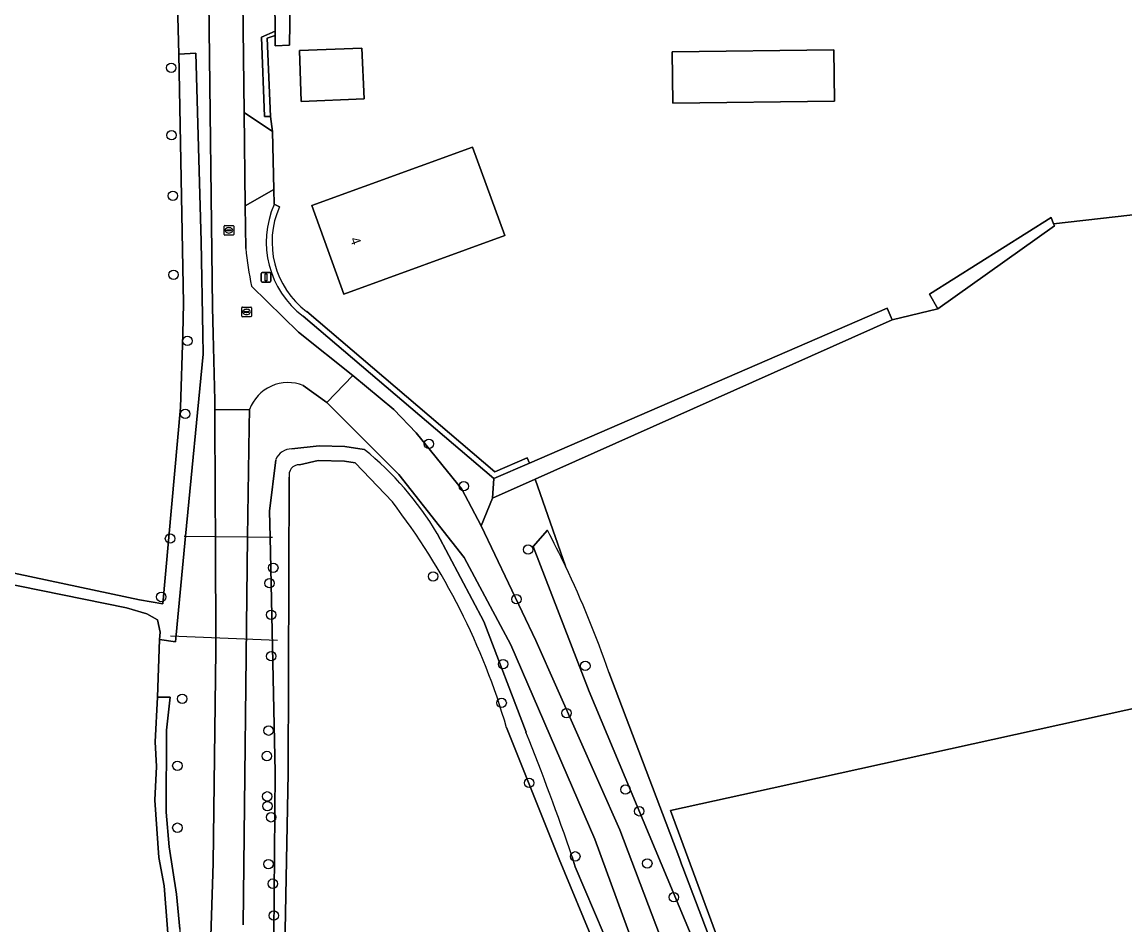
# Model space of a CAD drawing. Extents: x 163859 to 164644, y 379566 to 382155.
# Drawn here: x 164422.2 to 164536.6, y 381404.3 to 381497.9 of the extents above; entities that cross this region are included whole.
import ezdxf

# ---------------------------------------------------------------- set-up
doc = ezdxf.new("R2010")
doc.units = 0
for name, color, linetype in [('IMGEO_Boom', 7, 'Continuous'), ('IMGEO_Brandkraan', 7, 'Continuous'), ('IMGEO_Duiker', 7, 'Continuous'), ('IMGEO_Erf', 7, 'Continuous'), ('IMGEO_Grasland_agrarisch', 7, 'Continuous'), ('IMGEO_Grasland_overig', 7, 'Continuous'), ('IMGEO_Groenvoorziening', 7, 'Continuous'), ('IMGEO_Haag', 7, 'Continuous'), ('IMGEO_Lichtmast', 7, 'Continuous'), ('IMGEO_Loofbos', 7, 'Continuous'), ('IMGEO_Pand', 7, 'Continuous'), ('IMGEO_Pand_nummerreeks', 7, 'Continuous'), ('IMGEO_Rijbaan_lokaal_gesloten', 7, 'Continuous'), ('IMGEO_Rijbaan_lokaal_onverhard', 7, 'Continuous'), ('IMGEO_Rioolput', 7, 'Continuous'), ('IMGEO_Voetpad_open', 7, 'Continuous'), ('IMGEO_Waterloop', 7, 'Continuous')]:
    doc.layers.add(name, color=color, linetype=linetype)

msp = doc.modelspace()

# ---------------------------------------------------------------- linework, layer by layer
at = {"layer": 'IMGEO_Boom'}
for centre in [(164437.68, 381493.12), (164437.72, 381486.12), (164437.86, 381479.85), (164437.93, 381471.66), (164439.36, 381464.81), (164439.13, 381457.24), (164464.41, 381454.14), (164468.02, 381449.75), (164437.56, 381444.32), (164474.7, 381443.18), (164448.27, 381441.3), (164464.84, 381440.4), (164447.88, 381439.7), (164436.65, 381438.27), (164473.49, 381438.04), (164448.04, 381436.43), (164448.05, 381432.13), (164472.1, 381431.32), (164480.63, 381431.13), (164438.82, 381427.72), (164471.95, 381427.29), (164478.67, 381426.24), (164447.78, 381424.42), (164447.61, 381421.79), (164438.32, 381420.78), (164474.8, 381419.01), (164484.79, 381418.31), (164447.64, 381417.61), (164447.66, 381416.6), (164486.22, 381416.06), (164448.04, 381415.44), (164438.32, 381414.36), (164479.59, 381411.39), (164447.77, 381410.59), (164487.06, 381410.66), (164448.22, 381408.56), (164489.8, 381407.16), (164448.32, 381405.25)]:
    msp.add_circle(centre, 0.489, dxfattribs=at)
at = {"layer": 'IMGEO_Brandkraan'}
for p, q in [((164445, 381467.39), (164445, 381468.24)), ((164445.07, 381468.31), (164445.92, 381468.31)), ((164445.48, 381468.09), (164445.51, 381468.09)), ((164446, 381468.24), (164446, 381467.39)), ((164445.92, 381467.31), (164445.07, 381467.31)), ((164445.25, 381467.81), (164445.25, 381467.82)), ((164445.69, 381467.77), (164445.29, 381467.77)), ((164445.3, 381467.86), (164445.7, 381467.86)), ((164445.51, 381467.53), (164445.48, 381467.53)), ((164445.74, 381467.82), (164445.74, 381467.81))]:
    msp.add_line(p, q, dxfattribs=at)
for points in [[(164445, 381467.39), (164445, 381468.24)], [(164445.07, 381468.31), (164445.92, 381468.31)], [(164446, 381468.24), (164446, 381467.39)], [(164445.92, 381467.31), (164445.07, 381467.31)]]:
    msp.add_lwpolyline(points, dxfattribs=at)
for centre, radius, start, end in [((164445.07, 381468.24), 0.0765, 91.552, 178.448), ((164445.07, 381468.24), 0.0765, 91.552, 178.448), ((164445.92, 381468.24), 0.0765, 1.552, 88.448), ((164445.92, 381468.24), 0.0765, 1.552, 88.448), ((164445.07, 381467.39), 0.0765, 181.552, 268.448), ((164445.07, 381467.39), 0.0765, 181.552, 268.448), ((164445.3, 381467.82), 0.0403, 85.8775, 175.7526), ((164445.29, 381467.81), 0.0366, 178.938, 274.7102), ((164445.7, 381467.81), 0.043, 264.8664, 352.4533), ((164445.7, 381467.82), 0.0386, 1.7309, 96.639), ((164445.92, 381467.39), 0.0765, 271.552, 358.448), ((164445.92, 381467.39), 0.0765, 271.552, 358.448)]:
    msp.add_arc(centre, radius, start, end, dxfattribs=at)
for centre, major_axis, ratio, start_param, end_param in [((164445.48, 381467.81), (-0.387, 0.002), 0.722429, 4.712389, 7.853982), ((164445.51, 381467.81), (-0.39, 0.002), 0.717154, 1.570796, 4.712389)]:
    msp.add_ellipse(centre, major_axis=major_axis, ratio=ratio, start_param=start_param, end_param=end_param, dxfattribs=at)
at = {"layer": 'IMGEO_Duiker'}
for points in [[(164439.02, 381444.59), (164439.18, 381444.59), (164442.26, 381444.54), (164445.61, 381444.5), (164447.94, 381444.47), (164448.19, 381444.46)], [(164437.61, 381434.25), (164448.69, 381433.81)]]:
    msp.add_lwpolyline(points, dxfattribs=at)
at = {"layer": 'IMGEO_Erf'}
for points in [[(164450.01, 381500), (164449.96, 381495.46), (164448.45, 381495.4), (164448.45, 381496.45), (164447.62, 381496.18), (164447.99, 381488.08), (164448.2, 381486.51), (164448.33, 381480.51), (164448.37, 381478.97), (164448.92, 381478.72)], [(164451.73, 381467.85), (164471.25, 381451.25), (164474.6, 381452.7), (164474.84, 381452.15), (164511.94, 381468.21), (164512.46, 381467.01), (164517.19, 381468.15), (164516.33, 381469.65), (164528.93, 381477.6), (164529.2, 381476.95), (164546.85, 381478.96), (164550.19, 381479.28), (164572.08, 381481.36), (164589.1, 381482.68), (164601.73, 381483.93), (164603.35, 381484.14), (164603.26, 381486.4), (164606.33, 381486.63), (164606.55, 381484.56), (164606.85, 381484.6), (164606.85, 381484.81), (164606.82, 381486.07), (164607.05, 381486.1), (164606.79, 381500)]]:
    msp.add_lwpolyline(points, dxfattribs=at)
for points in [[(164457.68, 381489.91), (164451.15, 381489.61), (164450.97, 381494.89), (164457.45, 381495.15)], [(164506.46, 381489.64), (164489.69, 381489.43), (164489.62, 381494.77), (164506.39, 381494.98)], [(164472.27, 381475.73), (164455.6, 381469.67), (164452.28, 381478.83), (164468.94, 381484.89)], [(164565.06, 381406.39), (164564.53, 381407.1), (164559.87, 381421.34), (164557.52, 381431.13), (164500, 381418.46), (164489.46, 381416.14), (164495.45, 381399.95), (164500, 381401.35), (164503.1, 381402.3), (164503.54, 381401.07), (164504.8, 381397.62), (164505.66, 381395.29), (164507.47, 381390.32), (164518.04, 381364.93), (164522.77, 381352.02), (164528.1, 381339.46), (164564.56, 381341.91), (164578.44, 381343.7), (164575.05, 381361.38)]]:
    msp.add_lwpolyline(points, close=True, dxfattribs=at)
msp.add_arc((164457.2, 381475.06), 9.06, 156.1781, 232.8221, dxfattribs=at)
at = {"layer": 'IMGEO_Grasland_agrarisch'}
msp.add_lwpolyline([(164483.06, 381430.48), (164490.42, 381411.1), (164490.61, 381410.59), (164490.75, 381410.23), (164494.4, 381400.61), (164495.14, 381398.66), (164503.54, 381401.07), (164503.1, 381402.3), (164500, 381401.35), (164495.45, 381399.95), (164489.46, 381416.14), (164500, 381418.46), (164557.52, 381431.13), (164557.45, 381431.4), (164557.26, 381432.21), (164549, 381466.6), (164546.85, 381478.96), (164529.2, 381476.95), (164529.29, 381476.74), (164517.19, 381468.15), (164512.46, 381467.01), (164475.43, 381450.48), (164478.57, 381441.47)], dxfattribs=at)
msp.add_arc((164385.47, 381397.01), 103.17, 18.9285, 25.5241, dxfattribs=at)
at = {"layer": 'IMGEO_Grasland_overig'}
msp.add_lwpolyline([(164448.45, 381496.92), (164447.04, 381496.29), (164447.36, 381488.05), (164447.99, 381488.08), (164447.62, 381496.18), (164448.45, 381496.45)], close=True, dxfattribs=at)
at = {"layer": 'IMGEO_Groenvoorziening'}
for points in [[(164437.62, 381342.51), (164440.93, 381376.03), (164442.03, 381410.67), (164442.31, 381432.69), (164442.26, 381444.54), (164442.24, 381448.35), (164442.22, 381457.68), (164442.22, 381458.62), (164442.05, 381465.53), (164441.98, 381468.27), (164441.6, 381500), (164440.42, 381600.95)], [(164438.34, 381499.7), (164438.46, 381494.53), (164440.25, 381494.63), (164440.8, 381475.11), (164440.95, 381465.52), (164440.98, 381463.45), (164439.18, 381444.59), (164438.14, 381433.63), (164436.48, 381433.86), (164436.26, 381427.88), (164437.58, 381427.9), (164437.21, 381424.46), (164437.16, 381415.96), (164437.47, 381412.38), (164438.23, 381407.47), (164438.58, 381403.85), (164438.66, 381393.57), (164438.49, 381387.99), (164438.01, 381382.93), (164434.81, 381360.28), (164434.48, 381356.02), (164434.38, 381351.46), (164434.92, 381340.08), (164434.91, 381333.02)], [(164448.37, 381478.97), (164448.33, 381480.51), (164445.36, 381478.81), (164445.42, 381474.39)], [(164448.92, 381478.72), (164448.37, 381478.97)], [(164446.02, 381470.48), (164450.9, 381465.73), (164456.53, 381461.21), (164460.78, 381457.7), (164463.09, 381455.28), (164467.82, 381449.45), (164469.83, 381445.64), (164471, 381448.5), (164471.14, 381450.55), (164451.35, 381467.38)], [(164451.35, 381467.38), (164471.14, 381450.55), (164474.84, 381452.15), (164474.6, 381452.7), (164471.25, 381451.25), (164451.73, 381467.85)], [(164453.83, 381458.42), (164451.38, 381460.19)], [(164445.79, 381457.7), (164445.75, 381455.9), (164445.61, 381444.5), (164445.14, 381404.29)], [(164479.27, 381411.35), (164479.59, 381410.3), (164483.6, 381400.91), (164486.37, 381393.84), (164485.77, 381393.51), (164485.33, 381393.26), (164486.82, 381389.49), (164487.45, 381389.67), (164488.22, 381389.88), (164490.06, 381391.38), (164489.58, 381392.13), (164488.52, 381394.29), (164481.62, 381413.16), (164472.89, 381433.3), (164468.06, 381442.36), (164461.3, 381450.96), (164453.83, 381458.42)], [(164450.2, 381453.62), (164453.04, 381453.95), (164455.68, 381453.86), (164457.71, 381453.56)], [(164444.13, 381379.08), (164441.34, 381342.21), (164440.75, 381334.49), (164440.65, 381333.45), (164440.79, 381332.88), (164440.97, 381332.32), (164441.21, 381331.78), (164441.49, 381331.26), (164441.81, 381330.78), (164442.18, 381330.32), (164442.58, 381329.9), (164443.03, 381329.51), (164443.5, 381329.17), (164443.79, 381334.56), (164444.19, 381340.22), (164444.31, 381342.24), (164444.37, 381343.32), (164446.95, 381371.56), (164448.25, 381394.83), (164448.45, 381420.11), (164447.94, 381444.47), (164447.88, 381447.15), (164448.54, 381452.5)], [(164460.62, 381448.13), (164456.76, 381452.17), (164455.65, 381452.33), (164452.93, 381452.41), (164450.97, 381451.98)], [(164449.93, 381450.68), (164449.82, 381420.02), (164449.32, 381394.65), (164447.9, 381371.31), (164445.92, 381344.04), (164444.37, 381343.32), (164444.31, 381342.24), (164510.51, 381342.79), (164511.93, 381342.81)], [(164478.57, 381441.47), (164475.43, 381450.48), (164471, 381448.5), (164469.83, 381445.64), (164475.49, 381433.77), (164484.2, 381414.14), (164488.82, 381402.01), (164489.26, 381401.03), (164489.95, 381399.53), (164491.62, 381398.45), (164493.32, 381397.48), (164495.95, 381396.49), (164496.96, 381396.31), (164498.9, 381396.14), (164504.8, 381397.62), (164503.54, 381401.07), (164495.14, 381398.66), (164494.4, 381400.61), (164492.84, 381400.24), (164481.04, 381428.46)], [(164481.04, 381428.46), (164475.23, 381443.5), (164476.7, 381445.19)], [(164465.27, 381444.86), (164470.11, 381435.74), (164474.48, 381424.25)], [(164434.19, 381336.08), (164433.57, 381357.04), (164434.19, 381362.6), (164436.96, 381381.93), (164437.41, 381387.54), (164437.63, 381399.41), (164436.95, 381408.32), (164436.41, 381411.28), (164435.98, 381417.22), (164436.15, 381420.7), (164436.03, 381423.26), (164436.26, 381427.88), (164436.48, 381433.86), (164436.54, 381434.61), (164436.27, 381435.91), (164435.14, 381436.53), (164433.06, 381437.13), (164419.72, 381439.84)], [(164477.93, 381411.1), (164472.47, 381424.73)], [(164491.37, 381379.95), (164486.82, 381389.49), (164485.33, 381393.26), (164477.93, 381411.1)]]:
    msp.add_lwpolyline(points, dxfattribs=at)
msp.add_lwpolyline([(164448.2, 381486.51), (164447.99, 381488.08), (164447.36, 381488.05), (164447.04, 381496.29), (164448.45, 381496.92), (164448.44, 381500), (164448.42, 381507.52), (164450.1, 381507.69), (164449.91, 381509.12), (164448.27, 381509.34), (164448.43, 381516.36), (164450.07, 381516.57), (164450.68, 381517.67), (164444.92, 381515.57), (164445.11, 381500), (164445.25, 381488.48)], close=True, dxfattribs=at)
for centre, radius, start, end in [((164457.2, 381475.06), 9.66, 156.1754, 232.7263), ((164457.2, 381475.06), 9.66, 156.1754, 232.7263), ((164457.2, 381475.06), 9.06, 156.1781, 232.8221), ((164479.34, 381477.6), 34.08, 185.4069, 192.0479), ((164449.81, 381456.2), 4.29, 68.4859, 159.4524), ((164450.14, 381451.91), 1.71, 88.1681, 159.72), ((164436.5, 381427.49), 33.61, 31.1211, 50.8769), ((164450.97, 381450.91), 1.07, 90.0825, 192.4044), ((164404.37, 381404.95), 70.91, 16.1952, 37.5056), ((164385.55, 381397.06), 103.07, 25.5187, 27.833), ((164227.29, 381325.01), 266.36, 18.9147, 21.8737)]:
    msp.add_arc(centre, radius, start, end, dxfattribs=at)
at = {"layer": 'IMGEO_Haag'}
for points in [[(164448.92, 381478.72), (164448.37, 381478.97)], [(164451.35, 381467.38), (164471.14, 381450.55), (164474.84, 381452.15), (164474.6, 381452.7), (164471.25, 381451.25), (164451.73, 381467.85)]]:
    msp.add_lwpolyline(points, dxfattribs=at)
for radius, start, end in [(9.66, 156.1754, 232.7263), (9.06, 156.1781, 232.8221)]:
    msp.add_arc((164457.2, 381475.06), radius, start, end, dxfattribs=at)
at = {"layer": 'IMGEO_Lichtmast'}
for p, q in [((164447.02, 381471), (164447.02, 381471.8)), ((164447.02, 381471.8), (164447.02, 381471)), ((164447.12, 381471.9), (164447.91, 381471.9)), ((164447.91, 381471.9), (164447.12, 381471.9)), ((164448.01, 381471.8), (164448.01, 381471)), ((164448.01, 381471), (164448.01, 381471.8)), ((164447.91, 381470.9), (164447.12, 381470.9)), ((164447.12, 381470.9), (164447.91, 381470.9))]:
    msp.add_line(p, q, dxfattribs=at)
msp.add_lwpolyline([(164447.44, 381471.77), (164447.59, 381471.77), (164447.59, 381471.02), (164447.44, 381471.02), (164447.44, 381471.77)], dxfattribs=at)
for centre, start, end in [((164447.12, 381471.8), 90, 180), ((164447.12, 381471.8), 90, 180), ((164447.91, 381471.8), 0, 90), ((164447.91, 381471.8), 360, 90), ((164447.12, 381471), 180, 270), ((164447.12, 381471), 180, 270), ((164447.91, 381471), 270, 0), ((164447.91, 381471), 270, 0)]:
    msp.add_arc(centre, 0.1, start, end, dxfattribs=at)
at = {"layer": 'IMGEO_Loofbos'}
msp.add_lwpolyline([(164404.03, 381484.15), (164404.39, 381484.3), (164405.03, 381484.38), (164405.68, 381484.15), (164406.25, 381482.86), (164406.64, 381480.23), (164406.59, 381477.76), (164410.1, 381453.56), (164411.9, 381445.09), (164412.65, 381443.51), (164412.09, 381443.12), (164411.28, 381442.54), (164413.32, 381439.94), (164414.31, 381440.63), (164416.58, 381441.28), (164418.61, 381441.32), (164434.38, 381437.96), (164436.81, 381437.57), (164438.64, 381457.92), (164438.87, 381465.51), (164438.97, 381468.71), (164438.46, 381494.53), (164438.34, 381499.7)], dxfattribs=at)
at = {"layer": 'IMGEO_Pand'}
for points in [[(164451.15, 381489.61), (164457.68, 381489.91), (164457.45, 381495.15), (164450.97, 381494.89)], [(164506.39, 381494.98), (164489.62, 381494.77), (164489.69, 381489.43), (164506.46, 381489.64)], [(164455.6, 381469.67), (164472.27, 381475.73), (164468.94, 381484.89), (164452.28, 381478.83)]]:
    msp.add_lwpolyline(points, close=True, dxfattribs=at)
at = {"layer": 'IMGEO_Rijbaan_lokaal_gesloten'}
for points in [[(164445.42, 381474.39), (164445.36, 381478.81), (164445.25, 381488.48), (164445.11, 381500), (164444.92, 381515.57), (164444.8, 381525.85), (164443.88, 381602.47)], [(164440.42, 381600.95), (164441.6, 381500), (164441.98, 381468.27), (164442.05, 381465.53), (164442.22, 381458.62), (164442.22, 381457.68), (164445.79, 381457.7)], [(164451.38, 381460.19), (164453.83, 381458.42), (164456.53, 381461.21), (164450.9, 381465.73), (164446.02, 381470.48)], [(164445.14, 381404.29), (164445.61, 381444.5), (164445.75, 381455.9), (164445.79, 381457.7), (164442.22, 381457.68), (164442.24, 381448.35), (164442.26, 381444.54), (164442.31, 381432.69), (164442.03, 381410.67), (164440.93, 381376.03), (164437.62, 381342.51), (164436.86, 381328.83), (164436.27, 381323.37), (164435.38, 381319.58), (164433.55, 381313.72), (164431.24, 381307.56), (164428.74, 381302.37), (164431.96, 381299.66)]]:
    msp.add_lwpolyline(points, dxfattribs=at)
for centre, radius, start, end in [((164479.34, 381477.6), 34.08, 185.4069, 192.0479), ((164449.81, 381456.2), 4.29, 68.4859, 159.4524)]:
    msp.add_arc(centre, radius, start, end, dxfattribs=at)
at = {"layer": 'IMGEO_Rijbaan_lokaal_onverhard'}
msp.add_lwpolyline([(164488.82, 381402.01), (164484.2, 381414.14), (164475.49, 381433.77), (164469.83, 381445.64), (164467.82, 381449.45), (164463.09, 381455.28), (164460.78, 381457.7), (164456.53, 381461.21), (164453.83, 381458.42), (164461.3, 381450.96), (164468.06, 381442.36), (164472.89, 381433.3), (164481.62, 381413.16), (164488.52, 381394.29)], dxfattribs=at)
at = {"layer": 'IMGEO_Rioolput'}
for p, q in [((164443.16, 381475.84), (164443.16, 381476.69)), ((164443.24, 381476.77), (164444.09, 381476.77)), ((164443.42, 381476.26), (164443.42, 381476.27)), ((164443.86, 381476.22), (164443.46, 381476.22)), ((164443.47, 381476.31), (164443.86, 381476.31)), ((164443.65, 381476.55), (164443.68, 381476.55)), ((164443.67, 381475.99), (164443.65, 381475.99)), ((164443.91, 381476.27), (164443.91, 381476.26)), ((164444.16, 381476.69), (164444.16, 381475.84)), ((164444.09, 381475.77), (164443.24, 381475.77))]:
    msp.add_line(p, q, dxfattribs=at)
for points in [[(164443.16, 381475.84), (164443.16, 381476.69)], [(164443.24, 381476.77), (164444.09, 381476.77)], [(164444.16, 381476.69), (164444.16, 381475.84)], [(164444.09, 381475.77), (164443.24, 381475.77)]]:
    msp.add_lwpolyline(points, dxfattribs=at)
for centre, radius, start, end in [((164443.24, 381476.69), 0.0765, 91.552, 178.448), ((164443.24, 381476.69), 0.0765, 91.552, 178.448), ((164443.46, 381476.27), 0.0403, 85.8775, 175.7526), ((164443.46, 381476.26), 0.0366, 178.938, 274.7102), ((164443.87, 381476.27), 0.0386, 1.7309, 96.639), ((164443.86, 381476.27), 0.043, 264.8664, 352.4533), ((164444.09, 381476.69), 0.0765, 1.552, 88.448), ((164444.09, 381476.69), 0.0765, 1.552, 88.448), ((164443.24, 381475.84), 0.0765, 181.552, 268.448), ((164443.24, 381475.84), 0.0765, 181.552, 268.448), ((164444.09, 381475.84), 0.0765, 271.552, 358.448), ((164444.09, 381475.84), 0.0765, 271.552, 358.448)]:
    msp.add_arc(centre, radius, start, end, dxfattribs=at)
for centre, major_axis, ratio, start_param, end_param in [((164443.65, 381476.27), (-0.387, 0.002), 0.722429, 4.712389, 7.853982), ((164443.67, 381476.27), (-0.39, 0.002), 0.717154, 1.570796, 4.712389)]:
    msp.add_ellipse(centre, major_axis=major_axis, ratio=ratio, start_param=start_param, end_param=end_param, dxfattribs=at)
at = {"layer": 'IMGEO_Voetpad_open'}
msp.add_lwpolyline([(164448.2, 381486.51), (164445.25, 381488.48), (164445.36, 381478.81), (164448.33, 381480.51)], close=True, dxfattribs=at)
at = {"layer": 'IMGEO_Waterloop'}
for points in [[(164448.45, 381496.45), (164448.45, 381495.4), (164449.96, 381495.46), (164450.01, 381500), (164450.1, 381507.69), (164448.42, 381507.52), (164448.44, 381500), (164448.45, 381496.92)], [(164414.31, 381440.63), (164416.47, 381439.65), (164416.98, 381439.9), (164417.94, 381440.02), (164419.72, 381439.84), (164433.06, 381437.13), (164435.14, 381436.53), (164436.27, 381435.91), (164436.54, 381434.61), (164436.48, 381433.86), (164438.14, 381433.63), (164439.18, 381444.59), (164440.98, 381463.45), (164440.95, 381465.52), (164440.8, 381475.11), (164440.25, 381494.63), (164438.46, 381494.53), (164438.97, 381468.71), (164438.87, 381465.51), (164438.64, 381457.92), (164436.81, 381437.57), (164434.38, 381437.96), (164418.61, 381441.32), (164416.58, 381441.28)], [(164528.93, 381477.6), (164516.33, 381469.65), (164517.19, 381468.15), (164529.29, 381476.74), (164529.2, 381476.95)], [(164475.43, 381450.48), (164512.46, 381467.01), (164511.94, 381468.21), (164474.84, 381452.15), (164471.14, 381450.55), (164471, 381448.5)]]:
    msp.add_lwpolyline(points, close=True, dxfattribs=at)
for points in [[(164457.71, 381453.56), (164455.68, 381453.86), (164453.04, 381453.95), (164450.2, 381453.62)], [(164448.54, 381452.5), (164447.88, 381447.15), (164447.94, 381444.47), (164448.45, 381420.11), (164448.25, 381394.83), (164446.95, 381371.56), (164444.37, 381343.32), (164445.92, 381344.04), (164447.9, 381371.31), (164449.32, 381394.65), (164449.82, 381420.02), (164449.93, 381450.68)], [(164450.97, 381451.98), (164452.93, 381452.41), (164455.65, 381452.33), (164456.76, 381452.17), (164460.62, 381448.13)], [(164476.7, 381445.19), (164475.23, 381443.5), (164481.04, 381428.46), (164492.84, 381400.24), (164494.4, 381400.61), (164490.75, 381410.23), (164490.61, 381410.59), (164490.42, 381411.1), (164483.06, 381430.48)], [(164474.48, 381424.25), (164470.11, 381435.74), (164465.27, 381444.86)], [(164438.58, 381403.85), (164438.23, 381407.47), (164437.47, 381412.38), (164437.16, 381415.96), (164437.21, 381424.46), (164437.58, 381427.9), (164436.26, 381427.88), (164436.03, 381423.26), (164436.15, 381420.7), (164435.98, 381417.22), (164436.41, 381411.28), (164436.95, 381408.32), (164437.63, 381399.41)], [(164472.47, 381424.73), (164477.93, 381411.1), (164485.33, 381393.26), (164485.77, 381393.51), (164486.37, 381393.84), (164483.6, 381400.91), (164479.59, 381410.3), (164479.27, 381411.35)]]:
    msp.add_lwpolyline(points, dxfattribs=at)
for centre, radius, start, end in [((164450.14, 381451.91), 1.71, 88.1681, 159.72), ((164436.5, 381427.49), 33.61, 31.1211, 50.8769), ((164450.97, 381450.91), 1.07, 90.0825, 192.4044), ((164404.37, 381404.95), 70.91, 16.1952, 37.5056), ((164385.55, 381397.06), 103.07, 25.5187, 27.833), ((164385.47, 381397.01), 103.17, 18.9285, 25.5241), ((164227.29, 381325.01), 266.36, 18.9147, 21.8737)]:
    msp.add_arc(centre, radius, start, end, dxfattribs=at)

# ---------------------------------------------------------------- texts
at = {"layer": 'IMGEO_Pand_nummerreeks'}
msp.add_text('4', height=1, rotation=289.932, dxfattribs=at).set_placement((164456.22, 381475.36))

doc.saveas('drawing.dxf')
